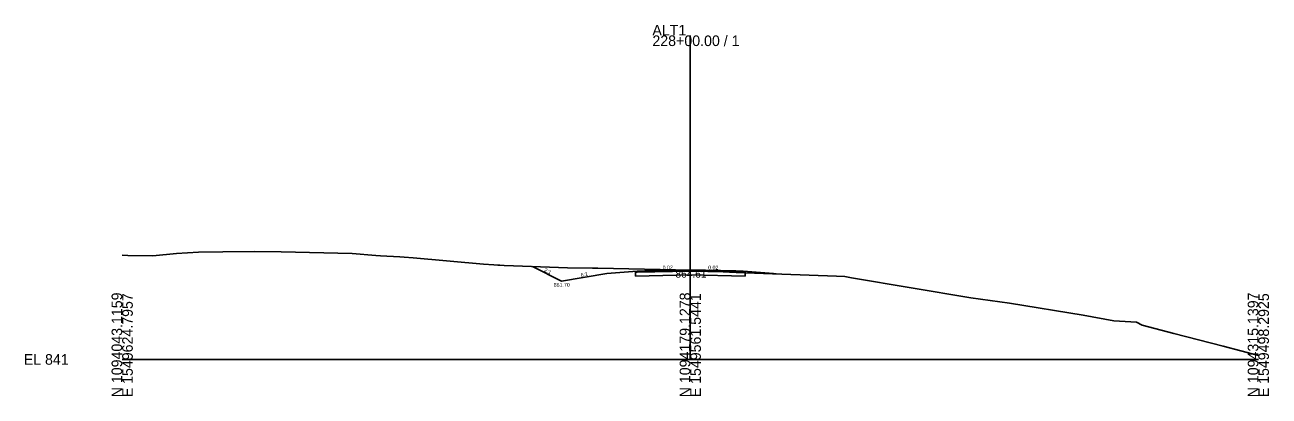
# Model space of a CAD drawing. Extents: x -26 to 1303, y -2510 to 19574.
# Drawn here: x 974.3 to 1302.8, y 3490.3 to 3588.4 of the extents above; entities that cross this region are included whole.
import ezdxf

# ---------------------------------------------------------------- set-up
doc = ezdxf.new("R2010")
doc.units = 0
for name, color, linetype in [('Default', 7, 'Continuous'), ('RD_GPK_XS_Cell', 7, 'Continuous'), ('RD_XS_Base', 7, 'Continuous'), ('RD_XS_ExGround', 7, 'Continuous'), ('RD_XS_Greenside', 7, 'Continuous'), ('RD_XS_Pave', 7, 'Continuous'), ('RD_XS_TieSlope', 7, 'Continuous'), ('RD_XS_TX_Ditch', 7, 'Continuous'), ('RD_XS_TX_Elev_EX', 7, 'Continuous'), ('RD_XS_TX_Slope', 7, 'Continuous')]:
    doc.layers.add(name, color=color, linetype=linetype)

msp = doc.modelspace()

# ---------------------------------------------------------------- linework, layer by layer
at = {"layer": 'RD_GPK_XS_Cell'}
for p, q in [((1150, 3500), (1150, 3585.6)), ((1000, 3500), (1150, 3500)), ((1150, 3500), (1300, 3500))]:
    msp.add_line(p, q, dxfattribs=at)
at = {"layer": 'RD_XS_Base'}
for points in [[(1135.5, 3523.04), (1136, 3523.05), (1150, 3523.33), (1164, 3523.05), (1164.5, 3523.04)], [(1135.5, 3522.04), (1135.5, 3523.04)], [(1164.5, 3522.04), (1150, 3522.33), (1135.5, 3522.04)], [(1164.5, 3523.04), (1164.5, 3522.04)]]:
    msp.add_lwpolyline(points, dxfattribs=at)
at = {"layer": 'RD_XS_ExGround'}
msp.add_lwpolyline([(1000, 3527.55), (1001.51, 3527.45), (1008.07, 3527.35), (1014.32, 3528), (1020.12, 3528.38), (1026.59, 3528.45), (1034.91, 3528.53), (1042.01, 3528.46), (1060.75, 3527.97), (1067.01, 3527.45), (1068.2, 3527.35), (1073.33, 3527.07), (1074.44, 3526.99), (1076.81, 3526.85), (1095.41, 3525.2), (1098.12, 3524.97), (1099.19, 3524.9), (1099.7, 3524.87), (1100.89, 3524.8), (1103.3, 3524.71), (1117.61, 3524.2), (1124.19, 3524.11), (1124.99, 3524.11), (1125.57, 3524.12), (1150.26, 3523.6), (1155.18, 3523.31), (1162.11, 3522.99), (1188.6, 3521.98), (1190.79, 3521.91), (1192.54, 3521.6), (1224.1, 3516.32), (1234.32, 3514.87), (1253.71, 3511.74), (1261.82, 3510.23), (1267.78, 3509.84), (1269.35, 3509.07), (1277.69, 3506.83), (1290.68, 3503.49), (1300, 3501.08)], dxfattribs=at)
at = {"layer": 'RD_XS_Greenside'}
for points in [[(1128, 3522.7), (1116, 3520.7)], [(1136, 3523.36), (1128, 3522.7)], [(1164, 3523.36), (1172, 3522.7)], [(1172, 3522.7), (1172.64, 3522.59)]]:
    msp.add_lwpolyline(points, dxfattribs=at)
at = {"layer": 'RD_XS_Pave'}
for points in [[(1136, 3523.36), (1138, 3523.4), (1150, 3523.64), (1162, 3523.4), (1164, 3523.36)], [(1136, 3523.21), (1150, 3523.49), (1164, 3523.21)], [(1164, 3523.21), (1150, 3523.49), (1136, 3523.21)], [(1136, 3523.21), (1136, 3523.36)], [(1164, 3523.05), (1150, 3523.33), (1136, 3523.05)], [(1136, 3523.05), (1136, 3523.21)], [(1164, 3523.36), (1164, 3523.21)], [(1164, 3523.21), (1164, 3523.05)]]:
    msp.add_lwpolyline(points, dxfattribs=at)
at = {"layer": 'RD_XS_TieSlope'}
msp.add_lwpolyline([(1116, 3520.7), (1108.34, 3524.53)], dxfattribs=at)

# ---------------------------------------------------------------- texts
at = {"layer": 'Default'}
msp.add_text('-', height=0.0001, dxfattribs=at).set_placement((1000, 3500))
at = {"layer": 'RD_GPK_XS_Cell'}
for s, p in [('ALT1', (1140, 3585.6)), ('228+00.00 / 1', (1140, 3582.8)), ('EL 841', (974, 3498.6))]:
    msp.add_text(s, height=2.8, dxfattribs=at).set_placement(p)
for s, p in [('N 1094043.1159', (1000, 3490)), ('E 1549624.7957', (1002.8, 3490)), ('N 1094179.1278', (1150, 3490)), ('E 1549561.5441', (1152.8, 3490)), ('N 1094315.1397', (1300, 3490)), ('E 1549498.2925', (1302.8, 3490))]:
    msp.add_text(s, height=2.8, rotation=90, dxfattribs=at).set_placement(p)
at = {"layer": 'RD_XS_TX_Ditch'}
msp.add_text('861.70', height=1, dxfattribs=at).set_placement((1113.95, 3519.2))
at = {"layer": 'RD_XS_TX_Elev_EX'}
msp.add_text('864.61', height=2, dxfattribs=at).set_placement((1146.09, 3521.61))
at = {"layer": 'RD_XS_TX_Slope'}
for s, rotation, p in [('2:1', 333.4349, (1111.3, 3523.32)), ('6:1', 9.4642, (1121.15, 3521.81)), ('0.02', 1.1458, (1142.71, 3523.75)), ('0.02', 358.8542, (1154.72, 3523.8))]:
    msp.add_text(s, height=1, rotation=rotation, dxfattribs=at).set_placement(p)

doc.saveas('drawing.dxf')
